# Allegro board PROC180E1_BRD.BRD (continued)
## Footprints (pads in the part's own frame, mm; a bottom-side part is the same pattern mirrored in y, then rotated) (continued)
CON_RCAJACK3_RCJ-02X_S_S_T_16
  rect 2.692x2.692 hole 1.981: 1(0,0)
  round 2.362 hole 1.676: 2(5.15,1.6)
  round 2.692 hole 1.981: 3(10.3,0)
CON_SD9_MEM2052-00-195-00_S_R_S_2
  rect 0.787x1.499 smd: 1(1.94,-3.66) 2(0.84,-3.26) 3(-0.26,-3.66) 4(-1.36,-3.86) 5(-2.46,-3.66) 6(-3.56,-3.86) 7(-4.66,-3.66) 8(-5.76,-3.66)
  rect 0.991x0.94 smd: 9(-3.56,7.425)
  rect 1.397x1.905 smd: SH1(6.6,-6.95) SH2(-6.55,-5.95)
  rect 1.295x1.397 smd: SH3(0.75,7.2)
  rect 1.194x1.397 smd: SH4(-5.008,7.2)
CON_USBA4_629104151_S_R_S_7-4
  round 1.092 hole 1.219 unplated: (-2.5,2.965) (2.5,2.965)
  rect 1.194x3.2 smd: 1(-3.5,6.665) 2(-1,6.665) 3(1,6.665) 4(3.5,6.665)
  oval 1.397x3.708 hole 0.711x2.997: SH1(-6.4,3.465) SH2(6.4,3.465)
CON_USBC24_2012670_S_R_S_3-9
  rect 0.305x0.762 smd: A1(-3,4.056) A2(-2.5,4.056) A3(-2,4.056) A4(-1.5,4.056) A5(-1,4.056) A6(-0.5,4.056) A7(0.5,4.056) A8(1,4.056) A9(1.5,4.056) A10(2,4.056) A11(2.5,4.056) A12(3,4.056) B2(2.25,2.356) B3(1.75,2.356) B4(1.25,2.356) B5(0.75,2.356) B6(0.25,2.356) B7(-0.25,2.356) B8(-0.75,2.356) B9(-1.25,2.356) B10(-1.75,2.356) B11(-2.25,2.356)
  rect 0.94x0.762 smd: B1(3.05,2.356) B12(-3.05,2.356)
  oval 1.194x2.21 hole 0.61x1.575: SH1(-4.32,3.246) SH2(4.32,3.246)
  oval 1.194x3.708 hole 0.61x2.083: SH3(4.62,-2.114) SH4(-4.62,-2.114)
DFN10_19-68_120X120_1
  rect 0.787x0.305 smd: 1(-1.5,1) 2(-1.5,0.5) 3(-1.5,0) 4(-1.5,-0.5) 5(-1.5,-1) 6(1.5,-1) 7(1.5,-0.5) 8(1.5,0) 9(1.5,0.5) 10(1.5,1)
  rect 1.753x2.515 smd: 11(0,0)
DIO_DFN0201_0-4
  rect 0.229x0.381 smd: 1(-0.22,0) 2(0.22,0)
DIO_DFN0402_0-5
  rect 0.356x0.61 smd: 1(-0.34,0) 2(0.34,0)
DIO_SOD323_1
  rect 0.914x0.508 smd: 1(-1.25,0) 2(1.25,0)
DIO_SOT23_123
  rect 1.016x0.61 smd: 1(-1.15,0.95) 2(-1.15,-0.95) 3(1.15,0)
DIO_SOT323-3_1-1
  rect 0.838x0.457 smd: 1(-1.05,0.65) 2(-1.05,-0.65) 3(1.05,0)
DSBGA12_15-74_60X70_0-4
  round 0.279 smd: A1(-0.4,0.6) A2(0,0.6) A3(0.4,0.6) B1(-0.4,0.2) B2(0,0.2) B3(0.4,0.2) C1(-0.4,-0.2) C2(0,-0.2) C3(0.4,-0.2) D1(-0.4,-0.6) D2(0,-0.6) D3(0.4,-0.6)
EMIFIL_BLM15A_0402_0-6
  rect 0.61x0.61 smd: 1(-0.46,0) 2(0.46,0)
EMIFIL_BLM18K_0603
  rect 0.94x1.194 smd: 1(-0.825,0) 2(0.825,0)
EMIFIL_BLM18P_0603_0-8
  rect 0.991x0.991 smd: 1(-0.75,0) 2(0.75,0)
EMIFIL_NFM15CC_0402_0-5
  rect 0.305x0.305 smd: 1(-0.5,0) 3(0.5,0)
  rect 0.254x0.762 smd: 2(0,0)
EMIFIL_NFM18C_0603_1-4
  rect 0.61x0.61 smd: 1(-0.8,0) 3(0.8,0)
  rect 0.406x1.219 smd: 2(0,0)
FBGA484_31-49_710X710_2-7
  round 0.457 smd: A1(-8.4,8.4) A2(-7.6,8.4) A3(-6.8,8.4) A4(-6,8.4) A5(-5.2,8.4) A6(-4.4,8.4) A7(-3.6,8.4) A8(-2.8,8.4) A9(-2,8.4) A10(-1.2,8.4) A11(-0.4,8.4) A12(0.4,8.4) A13(1.2,8.4) A14(2,8.4) A15(2.8,8.4) A16(3.6,8.4) A17(4.4,8.4) A18(5.2,8.4) A19(6,8.4) A20(6.8,8.4) A21(7.6,8.4) A22(8.4,8.4) AA1(-8.4,-7.6) AA2(-7.6,-7.6) AA3(-6.8,-7.6) AA4(-6,-7.6) AA5(-5.2,-7.6) AA6(-4.4,-7.6) AA7(-3.6,-7.6) AA8(-2.8,-7.6) AA9(-2,-7.6) AA10(-1.2,-7.6) AA11(-0.4,-7.6) AA12(0.4,-7.6) AA13(1.2,-7.6) AA14(2,-7.6) AA15(2.8,-7.6) AA16(3.6,-7.6) AA17(4.4,-7.6) AA18(5.2,-7.6) AA19(6,-7.6) AA20(6.8,-7.6) AA21(7.6,-7.6) AA22(8.4,-7.6) AB1(-8.4,-8.4) AB2(-7.6,-8.4) AB3(-6.8,-8.4) AB4(-6,-8.4) AB5(-5.2,-8.4) AB6(-4.4,-8.4) AB7(-3.6,-8.4) AB8(-2.8,-8.4) AB9(-2,-8.4) AB10(-1.2,-8.4) AB11(-0.4,-8.4) AB12(0.4,-8.4) AB13(1.2,-8.4) AB14(2,-8.4) AB15(2.8,-8.4) AB16(3.6,-8.4) AB17(4.4,-8.4) AB18(5.2,-8.4) AB19(6,-8.4) AB20(6.8,-8.4) AB21(7.6,-8.4) AB22(8.4,-8.4) B1(-8.4,7.6) B2(-7.6,7.6) B3(-6.8,7.6) B4(-6,7.6) B5(-5.2,7.6) B6(-4.4,7.6) B7(-3.6,7.6) B8(-2.8,7.6) B9(-2,7.6) B10(-1.2,7.6) B11(-0.4,7.6) B12(0.4,7.6) B13(1.2,7.6) B14(2,7.6) B15(2.8,7.6) B16(3.6,7.6) B17(4.4,7.6) B18(5.2,7.6) B19(6,7.6) B20(6.8,7.6) B21(7.6,7.6) B22(8.4,7.6) C1(-8.4,6.8) C2(-7.6,6.8) C3(-6.8,6.8) C4(-6,6.8) C5(-5.2,6.8) C6(-4.4,6.8) C7(-3.6,6.8) C8(-2.8,6.8) C9(-2,6.8) C10(-1.2,6.8) C11(-0.4,6.8) C12(0.4,6.8) C13(1.2,6.8) C14(2,6.8) C15(2.8,6.8) C16(3.6,6.8) C17(4.4,6.8) C18(5.2,6.8) C19(6,6.8) C20(6.8,6.8) C21(7.6,6.8) C22(8.4,6.8) D1(-8.4,6) D2(-7.6,6) D3(-6.8,6) D4(-6,6) D5(-5.2,6) D6(-4.4,6) D7(-3.6,6) D8(-2.8,6) D9(-2,6) D10(-1.2,6) D11(-0.4,6) D12(0.4,6) D13(1.2,6) D14(2,6) D15(2.8,6) D16(3.6,6) D17(4.4,6) D18(5.2,6) D19(6,6) D20(6.8,6) D21(7.6,6) D22(8.4,6) E1(-8.4,5.2) E2(-7.6,5.2) E3(-6.8,5.2) E4(-6,5.2) E5(-5.2,5.2) E6(-4.4,5.2) E7(-3.6,5.2) E8(-2.8,5.2) E9(-2,5.2) E10(-1.2,5.2) E11(-0.4,5.2) E12(0.4,5.2) E13(1.2,5.2) E14(2,5.2) E15(2.8,5.2) E16(3.6,5.2) E17(4.4,5.2) E18(5.2,5.2) E19(6,5.2) E20(6.8,5.2) E21(7.6,5.2) E22(8.4,5.2) F1(-8.4,4.4) F2(-7.6,4.4) F3(-6.8,4.4) F4(-6,4.4) F5(-5.2,4.4) F6(-4.4,4.4) F7(-3.6,4.4) F8(-2.8,4.4) F9(-2,4.4) F10(-1.2,4.4) F11(-0.4,4.4) F12(0.4,4.4) F13(1.2,4.4) F14(2,4.4) F15(2.8,4.4) F16(3.6,4.4) F17(4.4,4.4) F18(5.2,4.4) F19(6,4.4) F20(6.8,4.4) F21(7.6,4.4) F22(8.4,4.4) G1(-8.4,3.6) G2(-7.6,3.6) G3(-6.8,3.6) G4(-6,3.6) G5(-5.2,3.6) G6(-4.4,3.6) G7(-3.6,3.6) G8(-2.8,3.6) G9(-2,3.6) G10(-1.2,3.6) G11(-0.4,3.6) G12(0.4,3.6) G13(1.2,3.6) G14(2,3.6) G15(2.8,3.6) G16(3.6,3.6) G17(4.4,3.6) G18(5.2,3.6) G19(6,3.6) G20(6.8,3.6) G21(7.6,3.6) G22(8.4,3.6) H1(-8.4,2.8) H2(-7.6,2.8) H3(-6.8,2.8) H4(-6,2.8) H5(-5.2,2.8) H6(-4.4,2.8) H7(-3.6,2.8) H8(-2.8,2.8) H9(-2,2.8) H10(-1.2,2.8) H11(-0.4,2.8) H12(0.4,2.8) H13(1.2,2.8) H14(2,2.8) H15(2.8,2.8) H16(3.6,2.8) H17(4.4,2.8) H18(5.2,2.8) H19(6,2.8) H20(6.8,2.8) H21(7.6,2.8) H22(8.4,2.8) J1(-8.4,2) J2(-7.6,2) J3(-6.8,2) J4(-6,2) J5(-5.2,2) J6(-4.4,2) J7(-3.6,2) J8(-2.8,2) J9(-2,2) J10(-1.2,2) J11(-0.4,2) J12(0.4,2) J13(1.2,2) J14(2,2) J15(2.8,2) J16(3.6,2) J17(4.4,2) J18(5.2,2) J19(6,2) J20(6.8,2) J21(7.6,2) J22(8.4,2) K1(-8.4,1.2) K2(-7.6,1.2) K3(-6.8,1.2) K4(-6,1.2) K5(-5.2,1.2) K6(-4.4,1.2) K7(-3.6,1.2) K8(-2.8,1.2) K9(-2,1.2) K10(-1.2,1.2) K11(-0.4,1.2) K12(0.4,1.2) K13(1.2,1.2) K14(2,1.2) K15(2.8,1.2) K16(3.6,1.2) K17(4.4,1.2) K18(5.2,1.2) K19(6,1.2) K20(6.8,1.2) K21(7.6,1.2) K22(8.4,1.2) L1(-8.4,0.4) L2(-7.6,0.4) L3(-6.8,0.4) L4(-6,0.4) L5(-5.2,0.4) L6(-4.4,0.4) L7(-3.6,0.4) L8(-2.8,0.4) L9(-2,0.4) L10(-1.2,0.4) L11(-0.4,0.4) L12(0.4,0.4) L13(1.2,0.4) L14(2,0.4) L15(2.8,0.4) L16(3.6,0.4) L17(4.4,0.4) L18(5.2,0.4) L19(6,0.4) L20(6.8,0.4) L21(7.6,0.4) L22(8.4,0.4) M1(-8.4,-0.4) M2(-7.6,-0.4) M3(-6.8,-0.4) M4(-6,-0.4) M5(-5.2,-0.4) M6(-4.4,-0.4) M7(-3.6,-0.4) M8(-2.8,-0.4) M9(-2,-0.4) M10(-1.2,-0.4) M11(-0.4,-0.4) M12(0.4,-0.4) M13(1.2,-0.4) M14(2,-0.4) M15(2.8,-0.4) M16(3.6,-0.4) M17(4.4,-0.4) M18(5.2,-0.4) M19(6,-0.4) M20(6.8,-0.4) M21(7.6,-0.4) M22(8.4,-0.4) N1(-8.4,-1.2) N2(-7.6,-1.2) N3(-6.8,-1.2) N4(-6,-1.2) N5(-5.2,-1.2) N6(-4.4,-1.2) N7(-3.6,-1.2) N8(-2.8,-1.2) N9(-2,-1.2) N10(-1.2,-1.2) N11(-0.4,-1.2) N12(0.4,-1.2) N13(1.2,-1.2) N14(2,-1.2) N15(2.8,-1.2) N16(3.6,-1.2) N17(4.4,-1.2) N18(5.2,-1.2) N19(6,-1.2) N20(6.8,-1.2) N21(7.6,-1.2) N22(8.4,-1.2) P1(-8.4,-2) P2(-7.6,-2) P3(-6.8,-2) P4(-6,-2) P5(-5.2,-2) P6(-4.4,-2) P7(-3.6,-2) P8(-2.8,-2) P9(-2,-2) P10(-1.2,-2) P11(-0.4,-2) P12(0.4,-2) P13(1.2,-2) P14(2,-2) P15(2.8,-2) P16(3.6,-2) P17(4.4,-2) P18(5.2,-2) P19(6,-2) P20(6.8,-2) P21(7.6,-2) P22(8.4,-2) R1(-8.4,-2.8) R2(-7.6,-2.8) R3(-6.8,-2.8) R4(-6,-2.8) R5(-5.2,-2.8) R6(-4.4,-2.8) R7(-3.6,-2.8) R8(-2.8,-2.8) R9(-2,-2.8) R10(-1.2,-2.8) R11(-0.4,-2.8) R12(0.4,-2.8) R13(1.2,-2.8) R14(2,-2.8) R15(2.8,-2.8) R16(3.6,-2.8) R17(4.4,-2.8) R18(5.2,-2.8) R19(6,-2.8) R20(6.8,-2.8) R21(7.6,-2.8) R22(8.4,-2.8) T1(-8.4,-3.6) T2(-7.6,-3.6) T3(-6.8,-3.6) T4(-6,-3.6) T5(-5.2,-3.6) T6(-4.4,-3.6) T7(-3.6,-3.6) T8(-2.8,-3.6) T9(-2,-3.6) T10(-1.2,-3.6) T11(-0.4,-3.6) T12(0.4,-3.6) T13(1.2,-3.6) T14(2,-3.6) T15(2.8,-3.6) T16(3.6,-3.6) T17(4.4,-3.6) T18(5.2,-3.6) T19(6,-3.6) T20(6.8,-3.6) T21(7.6,-3.6) T22(8.4,-3.6) U1(-8.4,-4.4) U2(-7.6,-4.4) U3(-6.8,-4.4) U4(-6,-4.4) U5(-5.2,-4.4) U6(-4.4,-4.4) U7(-3.6,-4.4) U8(-2.8,-4.4) U9(-2,-4.4) U10(-1.2,-4.4) U11(-0.4,-4.4) U12(0.4,-4.4) U13(1.2,-4.4) U14(2,-4.4) U15(2.8,-4.4) U16(3.6,-4.4) U17(4.4,-4.4) U18(5.2,-4.4) U19(6,-4.4) U20(6.8,-4.4) U21(7.6,-4.4) U22(8.4,-4.4) V1(-8.4,-5.2) V2(-7.6,-5.2) V3(-6.8,-5.2) V4(-6,-5.2) V5(-5.2,-5.2) V6(-4.4,-5.2) V7(-3.6,-5.2) V8(-2.8,-5.2) V9(-2,-5.2) V10(-1.2,-5.2) V11(-0.4,-5.2) V12(0.4,-5.2) V13(1.2,-5.2) V14(2,-5.2) V15(2.8,-5.2) V16(3.6,-5.2) V17(4.4,-5.2) V18(5.2,-5.2) V19(6,-5.2) V20(6.8,-5.2) V21(7.6,-5.2) V22(8.4,-5.2) W1(-8.4,-6) W2(-7.6,-6) W3(-6.8,-6) W4(-6,-6) W5(-5.2,-6) W6(-4.4,-6) W7(-3.6,-6) W8(-2.8,-6) W9(-2,-6) W10(-1.2,-6) W11(-0.4,-6) W12(0.4,-6) W13(1.2,-6) W14(2,-6) W15(2.8,-6) W16(3.6,-6) W17(4.4,-6) W18(5.2,-6) W19(6,-6) W20(6.8,-6) W21(7.6,-6) W22(8.4,-6) Y1(-8.4,-6.8) Y2(-7.6,-6.8) Y3(-6.8,-6.8) Y4(-6,-6.8) Y5(-5.2,-6.8) Y6(-4.4,-6.8) Y7(-3.6,-6.8) Y8(-2.8,-6.8) Y9(-2,-6.8) Y10(-1.2,-6.8) Y11(-0.4,-6.8) Y12(0.4,-6.8) Y13(1.2,-6.8) Y14(2,-6.8) Y15(2.8,-6.8) Y16(3.6,-6.8) Y17(4.4,-6.8) Y18(5.2,-6.8) Y19(6,-6.8) Y20(6.8,-6.8) Y21(7.6,-6.8) Y22(8.4,-6.8)
HDR_1X2_90120-0122_S_T_5-6
  rect 1.702x1.702 hole 1.016: 1(0,0)
  round 1.702 hole 1.016: 2(-2.54,0)
HDR_1X2_61300211121_S_T_8-6
  rect 1.803x1.803 hole 1.118: 1(0,0)
  round 1.803 hole 1.118: 2(-2.54,0)
HDR_1X3_100_S_T
  rect 1.803x1.803 hole 1.118: 1(0,0)
  round 1.803 hole 1.118: 2(-2.54,0) 3(-5.08,0)
HDR_1X6_61300611121_S_T_8-6
  rect 1.803x1.803 hole 1.118: 1(0,0)
  round 1.803 hole 1.118: 2(-2.54,0) 3(-5.08,0) 4(-7.62,0) 5(-10.16,0) 6(-12.7,0)
HDR_2X5_PEC05DAAN_S_T_8-6
  rect 1.702x1.702 hole 1.016: 1(0,0)
  round 1.702 hole 1.016: 2(0,2.54) 3(2.54,0) 4(2.54,2.54) 5(5.08,0) 6(5.08,2.54) 7(7.62,0) 8(7.62,2.54) 9(10.16,0) 10(10.16,2.54)
HDR_2X10_FTR-110-51-D-06_S_S_8-7
  rect 0.711x3.124 smd: 1(-5.715,-2.578) 2(-5.715,2.578) 3(-4.445,-2.578) 4(-4.445,2.578) 5(-3.175,-2.578) 7(-1.905,-2.578) 8(-1.905,2.578) 9(-0.635,-2.578) 10(-0.635,2.578) 11(0.635,-2.578) 12(0.635,2.578) 13(1.905,-2.578) 14(1.905,2.578) 15(3.175,-2.578) 16(3.175,2.578) 17(4.445,-2.578) 18(4.445,2.578) 19(5.715,-2.578) 20(5.715,2.578)
IND4_DLW21H_90X60_SMD_1-4
  rect 0.889x0.356 smd: 1(-0.85,-0.425) 2(0.85,-0.425) 3(0.85,0.425) 4(-0.85,0.425)
IND0806
  rect 1.219x1.803 smd: 1(-0.85,0) 2(0.85,0)
IND0806_1-2
  rect 1.219x1.803 smd: 1(-0.85,0) 2(0.85,0)
IND1210_1-2
  rect 1.346x2.794 smd: 1(-1.6,0) 2(1.6,0)
IND_XAL7070_300X310_SMD_7
  rect 1.93x6.502 smd: 1(-2.41,0) 2(2.41,0)
IND_XFL4020_170X170_SMD_2-1
  rect 0.991x3.404 smd: 1(-1.185,0) 2(1.185,0)
INDP1210
  rect 1.803x2.007 smd: 1(-1.4,0) 2(1.4,0)
LED_150040GS73220_40X20_SMD_0-4
  rect 0.406x0.457 smd: 1(-0.5,0) 2(0.5,0)
LED_150080VS75000_80X50_SMD_0-8
  rect 1.092x1.194 smd: 1(-1.05,0) 2(1.05,0)
LQFP64_19-68_390X390_1-6
  rect 1.499x0.305 smd: 1(-5.7,3.75) 2(-5.7,3.25) 3(-5.7,2.75) 4(-5.7,2.25) 5(-5.7,1.75) 6(-5.7,1.25) 7(-5.7,0.75) 8(-5.7,0.25) 9(-5.7,-0.25) 10(-5.7,-0.75) 11(-5.7,-1.25) 12(-5.7,-1.75) 13(-5.7,-2.25) 14(-5.7,-2.75) 15(-5.7,-3.25) 16(-5.7,-3.75) 33(5.7,-3.75) 34(5.7,-3.25) 35(5.7,-2.75) 36(5.7,-2.25) 37(5.7,-1.75) 38(5.7,-1.25) 39(5.7,-0.75) 40(5.7,-0.25) 41(5.7,0.25) 42(5.7,0.75) 43(5.7,1.25) 44(5.7,1.75) 45(5.7,2.25) 46(5.7,2.75) 47(5.7,3.25) 48(5.7,3.75)
  rect 0.305x1.499 smd: 17(-3.75,-5.7) 18(-3.25,-5.7) 19(-2.75,-5.7) 20(-2.25,-5.7) 21(-1.75,-5.7) 22(-1.25,-5.7) 23(-0.75,-5.7) 24(-0.25,-5.7) 25(0.25,-5.7) 26(0.75,-5.7) 27(1.25,-5.7) 28(1.75,-5.7) 29(2.25,-5.7) 30(2.75,-5.7) 31(3.25,-5.7) 32(3.75,-5.7) 49(3.75,5.7) 50(3.25,5.7) 51(2.75,5.7) 52(2.25,5.7) 53(1.75,5.7) 54(1.25,5.7) 55(0.75,5.7) 56(0.25,5.7) 57(-0.25,5.7) 58(-0.75,5.7) 59(-1.25,5.7) 60(-1.75,5.7) 61(-2.25,5.7) 62(-2.75,5.7) 63(-3.25,5.7) 64(-3.75,5.7)
MOD5_PLR135T10_10-3
  rect 1.575x1.575 hole 0.864: 1(0,0)
  round 1.575 hole 0.864: 2(-2.54,0) 3(-5.08,0)
  round 1.88 hole 1.168: 4(0,2.63) 5(-5.08,2.63)
MSOP8_25-59_125X125_1-1
  rect 1.448x0.457 smd: 1(-2.2,0.975) 2(-2.2,0.325) 3(-2.2,-0.325) 4(-2.2,-0.975) 5(2.2,-0.975) 6(2.2,-0.325) 7(2.2,0.325) 8(2.2,0.975)
MSOP10_19-68_120X120_1-1
  rect 1.448x0.305 smd: 1(-2.2,1) 2(-2.2,0.5) 3(-2.2,0) 4(-2.2,-0.5) 5(-2.2,-1) 6(2.2,-1) 7(2.2,-0.5) 8(2.2,0) 9(2.2,0.5) 10(2.2,1)
QFN20_19-68_160X160_0-9_EP2-7
  rect 0.787x0.305 smd: 1(-2,1) 2(-2,0.5) 3(-2,0) 4(-2,-0.5) 5(-2,-1) 11(2,-1) 12(2,-0.5) 13(2,0) 14(2,0.5) 15(2,1)
  rect 0.305x0.787 smd: 6(-1,-2) 7(-0.5,-2) 8(0,-2) 9(0.5,-2) 10(1,-2) 16(1,2) 17(0.5,2) 18(0,2) 19(-0.5,2) 20(-1,2)
  rect 2.692x2.692 smd: 21(0,0)
QFN24_19-68_220X140_1
  rect 0.838x0.279 smd: 1(-2.725,-0.75) 12(2.725,-0.75) 13(2.725,0.75) 24(-2.725,0.75)
  rect 0.279x0.838 smd: 2(-2.25,-1.725) 3(-1.75,-1.725) 4(-1.25,-1.725) 5(-0.75,-1.725) 6(-0.25,-1.725) 7(0.25,-1.725) 8(0.75,-1.725) 9(1.25,-1.725) 10(1.75,-1.725) 11(2.25,-1.725) 14(2.25,1.725) 15(1.75,1.725) 16(1.25,1.725) 17(0.75,1.725) 18(0.25,1.725) 19(-0.25,1.725) 20(-0.75,1.725) 21(-1.25,1.725) 22(-1.75,1.725) 23(-2.25,1.725)
  custom 0.508x0.508 smd: 25(0,0)
QFN24_TAD5212IRGER_160X160_1
  rect 0.787x0.305 smd: 1(-2,1.25) 2(-2,0.75) 3(-2,0.25) 4(-2,-0.25) 5(-2,-0.75) 6(-2,-1.25) 13(2,-1.25) 14(2,-0.75) 15(2,-0.25) 16(2,0.25) 17(2,0.75) 18(2,1.25)
  rect 0.305x0.787 smd: 7(-1.25,-2) 8(-0.75,-2) 9(-0.25,-2) 10(0.25,-2) 11(0.75,-2) 12(1.25,-2) 19(1.25,2) 20(0.75,2) 21(0.25,2) 22(-0.25,2) 23(-0.75,2) 24(-1.25,2)
  rect 2.21x2.21 smd: 25(0,0)
  rect 0.254x0.254 smd: A1(-1.725,1.725) A2(-1.725,-1.725) A3(1.725,-1.725) A4(1.725,1.725)
QFN32_19-68_200X200
  rect 0.838x0.305 smd: 1(-2.5,1.75) 2(-2.5,1.25) 3(-2.5,0.75) 4(-2.5,0.25) 5(-2.5,-0.25) 6(-2.5,-0.75) 7(-2.5,-1.25) 8(-2.5,-1.75) 17(2.5,-1.75) 18(2.5,-1.25) 19(2.5,-0.75) 20(2.5,-0.25) 21(2.5,0.25) 22(2.5,0.75) 23(2.5,1.25) 24(2.5,1.75)
  rect 0.305x0.838 smd: 9(-1.75,-2.5) 10(-1.25,-2.5) 11(-0.75,-2.5) 12(-0.25,-2.5) 13(0.25,-2.5) 14(0.75,-2.5) 15(1.25,-2.5) 16(1.75,-2.5) 25(1.75,2.5) 26(1.25,2.5) 27(0.75,2.5) 28(0.25,2.5) 29(-0.25,2.5) 30(-0.75,2.5) 31(-1.25,2.5) 32(-1.75,2.5)
  rect 3.556x3.556 smd: 33(0,0)
QFN32_19-68_200X200_0-8_EP3-6
  rect 0.787x0.305 smd: 1(-2.5,1.75) 2(-2.5,1.25) 3(-2.5,0.75) 4(-2.5,0.25) 5(-2.5,-0.25) 6(-2.5,-0.75) 7(-2.5,-1.25) 8(-2.5,-1.75) 17(2.5,-1.75) 18(2.5,-1.25) 19(2.5,-0.75) 20(2.5,-0.25) 21(2.5,0.25) 22(2.5,0.75) 23(2.5,1.25) 24(2.5,1.75)
  rect 0.305x0.787 smd: 9(-1.75,-2.5) 10(-1.25,-2.5) 11(-0.75,-2.5) 12(-0.25,-2.5) 13(0.25,-2.5) 14(0.75,-2.5) 15(1.25,-2.5) 16(1.75,-2.5) 25(1.75,2.5) 26(1.25,2.5) 27(0.75,2.5) 28(0.25,2.5) 29(-0.25,2.5) 30(-0.75,2.5) 31(-1.25,2.5) 32(-1.75,2.5)
  rect 3.607x3.607 smd: 33(0,0)
QFN48_19-68_280X280_1_EP5-4
  rect 0.813x0.305 smd: 1(-3.5,2.75) 2(-3.5,2.25) 3(-3.5,1.75) 4(-3.5,1.25) 5(-3.5,0.75) 6(-3.5,0.25) 7(-3.5,-0.25) 8(-3.5,-0.75) 9(-3.5,-1.25) 10(-3.5,-1.75) 11(-3.5,-2.25) 12(-3.5,-2.75) 25(3.5,-2.75) 26(3.5,-2.25) 27(3.5,-1.75) 28(3.5,-1.25) 29(3.5,-0.75) 30(3.5,-0.25) 31(3.5,0.25) 32(3.5,0.75) 33(3.5,1.25) 34(3.5,1.75) 35(3.5,2.25) 36(3.5,2.75)
  rect 0.305x0.813 smd: 13(-2.75,-3.5) 14(-2.25,-3.5) 15(-1.75,-3.5) 16(-1.25,-3.5) 17(-0.75,-3.5) 18(-0.25,-3.5) 19(0.25,-3.5) 20(0.75,-3.5) 21(1.25,-3.5) 22(1.75,-3.5) 23(2.25,-3.5) 24(2.75,-3.5) 37(2.75,3.5) 38(2.25,3.5) 39(1.75,3.5) 40(1.25,3.5) 41(0.75,3.5) 42(0.25,3.5) 43(-0.25,3.5) 44(-0.75,3.5) 45(-1.25,3.5) 46(-1.75,3.5) 47(-2.25,3.5) 48(-2.75,3.5)
  rect 5.41x5.41 smd: 49(0,0)
RES0201_0-5
  rect 0.356x0.33 smd: 1(-0.28,0) 2(0.28,0)
RES0402_0-5
  rect 0.559x0.635 smd: 1(-0.49,0) 2(0.49,0)
RES0603_0-75
  rect 0.635x0.991 smd: 1(-0.74,0) 2(0.74,0)
RES0805_0-75
  rect 1.194x1.448 smd: 1(-0.95,0) 2(0.95,0)
RES1206_1
  rect 1.067x1.753 smd: 1(-1.45,0) 2(1.45,0)
RES_CST0612_0612-4_0-9
  rect 0.991x2.311 smd: 1(-0.85,0.6) 4(0.85,0.6)
  rect 0.991x0.787 smd: 2(-0.85,-1.35) 3(0.85,-1.35)
RES_KRL3216T4_1206-4_0-7
  rect 1.143x0.356 smd: 1(-0.775,1.5) 4(0.775,1.5)
  rect 1.143x2.692 smd: 2(-0.775,-0.325) 3(0.775,-0.325)
RESA_EXB_0201-2_0-5
  rect 0.203x0.305 smd: 1(-0.25,-0.275) 2(0.25,-0.275) 3(0.25,0.275) 4(-0.25,0.275)
RESA_EXB_0201-4_0-5
  rect 0.203x0.305 smd: 1(-0.6,-0.275) 2(-0.2,-0.275) 3(0.2,-0.275) 4(0.6,-0.275) 5(0.6,0.275) 6(0.2,0.275) 7(-0.2,0.275) 8(-0.6,0.275)
SC70-5
  rect 0.94x0.406 smd: 1(-1.1,0.65) 2(-1.1,0) 3(-1.1,-0.65) 4(1.1,-0.65) 5(1.1,0.65)
SC70-5_1-1
  rect 0.94x0.406 smd: 1(-1.1,0.65) 2(-1.1,0) 3(-1.1,-0.65) 4(1.1,-0.65) 5(1.1,0.65)
SOIC8_1-8
  rect 1.549x0.61 smd: 1(-2.7,1.905) 2(-2.7,0.635) 3(-2.7,-0.635) 4(-2.7,-1.905) 5(2.7,-1.905) 6(2.7,-0.635) 7(2.7,0.635) 8(2.7,1.905)
SON6_19-68_40X60_PB_0-6
  rect 0.356x0.305 smd: 1(-0.3,0.5) 2(-0.3,0) 3(-0.3,-0.5) 4(0.3,-0.5) 5(0.3,0) 6(0.3,0.5)
SON6_25-59_85X85
  rect 0.61x0.356 smd: 1(-1.05,0.65) 2(-1.05,0) 3(-1.05,-0.65) 4(1.05,-0.65) 5(1.05,0) 6(1.05,0.65)
  rect 1.092x1.702 smd: 7(0,0)
SON6_25-59_85X85_0-8
  rect 0.61x0.356 smd: 1(-1.05,0.65) 2(-1.05,0) 3(-1.05,-0.65) 4(1.05,-0.65) 5(1.05,0) 6(1.05,0.65)
  rect 1.067x1.702 smd: 7(0,0)
SON6_CSD17313Q2_80X80
  rect 0.406x0.457 smd: 1(-0.65,-0.923) 2(0,-0.923) 3(0.65,-0.923) 4(0.65,0.923) 5(0,0.923) 6(-0.65,0.923)
  rect 0.406x0.864 smd: 7(0.65,0.096)
  rect 1.041x1.092 smd: 8(-0.325,0)
SON6_SN74LVC2G17_40X60_0-6
  rect 0.356x0.203 smd: 1(-0.275,0.5)
  rect 0.305x0.203 smd: 2(-0.3,0) 3(-0.3,-0.5) 4(0.3,-0.5) 5(0.3,0) 6(0.3,0.5)
SON8_25-59_130X130_1
  rect 0.762x0.356 smd: 1(-1.45,0.975) 2(-1.45,0.325) 3(-1.45,-0.325) 4(-1.45,-0.975) 5(1.45,-0.975) 6(1.45,-0.325) 7(1.45,0.325) 8(1.45,0.975)
  rect 1.753x2.515 smd: 9(0,0)
SOT23-5
  rect 0.889x0.559 smd: 1(-1.2,0.95) 2(-1.2,0) 3(-1.2,-0.95) 4(1.2,-0.95) 5(1.2,0.95)
SOT23-5_1-5
  rect 1.092x0.61 smd: 1(-1.3,0.95) 2(-1.3,0) 3(-1.3,-0.95) 4(1.3,-0.95) 5(1.3,0.95)
SOT23-6
  rect 1.041x0.61 smd: 1(-1.35,0.95) 2(-1.35,0) 3(-1.35,-0.95) 4(1.35,-0.95) 5(1.35,0) 6(1.35,0.95)
SOT23-6_1-5
  rect 1.092x0.61 smd: 1(-1.35,0.95) 2(-1.35,0) 3(-1.35,-0.95) 4(1.35,-0.95) 5(1.35,0) 6(1.35,0.95)
SOT23-123_1-2
  rect 1.016x0.61 smd: 1(-1.15,0.95) 2(-1.15,-0.95) 3(1.15,0)
SOT553-5_0-6
  rect 0.66x0.254 smd: 1(-0.74,0.5) 2(-0.74,0) 3(-0.74,-0.5) 4(0.74,-0.5) 5(0.74,0.5)
SW4_49-99_150X230_SMD_2-7
  rect 0.762x1.27 smd: 1(-0.635,-3.81) 2(0.635,-3.81) 3(0.635,3.81) 4(-0.635,3.81)
SW4_100X216_200X200_SMD_4-2
  rect 1.27x1.27 smd: 1(-1.27,-2.75) 2(1.27,-2.75) 3(1.27,2.75) 4(-1.27,2.75)
SW16_416131160808_460X230_SMD_2-7
  rect 0.762x1.27 smd: 1(-4.445,-3.81) 2(-3.175,-3.81) 3(-1.905,-3.81) 4(-0.635,-3.81) 5(0.635,-3.81) 6(1.905,-3.81) 7(3.175,-3.81) 8(4.445,-3.81) 9(4.445,3.81) 10(3.175,3.81) 11(1.905,3.81) 12(0.635,3.81) 13(-0.635,3.81) 14(-1.905,3.81) 15(-3.175,3.81) 16(-4.445,3.81)
TO_SOT23-123
  rect 1.016x1.397 smd: 1(-0.95,-1.1) 2(0.95,-1.1) 3(0,1.1)
TP20_SMD
  round 0.457 smd: 1(0,0)
TP30_SMD
  round 0.762 smd: 1(0,0)
TP40_SMD
  round 1.016 smd: 1(0,0)
TP_40X65
  round 1.651 hole 1.016: 1(0,0)
TP_CIR40D30
  round 1.016 hole 0.762: 1(0,0)
TQFP48_19-68_280X280_1-2
  rect 1.499x0.305 smd: 1(-4.2,2.75) 2(-4.2,2.25) 3(-4.2,1.75) 4(-4.2,1.25) 5(-4.2,0.75) 6(-4.2,0.25) 7(-4.2,-0.25) 8(-4.2,-0.75) 9(-4.2,-1.25) 10(-4.2,-1.75) 11(-4.2,-2.25) 12(-4.2,-2.75) 25(4.2,-2.75) 26(4.2,-2.25) 27(4.2,-1.75) 28(4.2,-1.25) 29(4.2,-0.75) 30(4.2,-0.25) 31(4.2,0.25) 32(4.2,0.75) 33(4.2,1.25) 34(4.2,1.75) 35(4.2,2.25) 36(4.2,2.75)
  rect 0.305x1.499 smd: 13(-2.75,-4.2) 14(-2.25,-4.2) 15(-1.75,-4.2) 16(-1.25,-4.2) 17(-0.75,-4.2) 18(-0.25,-4.2) 19(0.25,-4.2) 20(0.75,-4.2) 21(1.25,-4.2) 22(1.75,-4.2) 23(2.25,-4.2) 24(2.75,-4.2) 37(2.75,4.2) 38(2.25,4.2) 39(1.75,4.2) 40(1.25,4.2) 41(0.75,4.2) 42(0.25,4.2) 43(-0.25,4.2) 44(-0.75,4.2) 45(-1.25,4.2) 46(-1.75,4.2) 47(-2.25,4.2) 48(-2.75,4.2)
TQFP128_15-74_550X550_1-2
  rect 1.499x0.203 smd: 1(-7.7,6.2) 2(-7.7,5.8) 3(-7.7,5.4) 4(-7.7,5) 5(-7.7,4.6) 6(-7.7,4.2) 7(-7.7,3.8) 8(-7.7,3.4) 9(-7.7,3) 10(-7.7,2.6) 11(-7.7,2.2) 12(-7.7,1.8) 13(-7.7,1.4) 14(-7.7,1) 15(-7.7,0.6) 16(-7.7,0.2) 17(-7.7,-0.2) 18(-7.7,-0.6) 19(-7.7,-1) 20(-7.7,-1.4) 21(-7.7,-1.8) 22(-7.7,-2.2) 23(-7.7,-2.6) 24(-7.7,-3) 25(-7.7,-3.4) 26(-7.7,-3.8) 27(-7.7,-4.2) 28(-7.7,-4.6) 29(-7.7,-5) 30(-7.7,-5.4) 31(-7.7,-5.8) 32(-7.7,-6.2) 65(7.7,-6.2) 66(7.7,-5.8) 67(7.7,-5.4) 68(7.7,-5) 69(7.7,-4.6) 70(7.7,-4.2) 71(7.7,-3.8) 72(7.7,-3.4) 73(7.7,-3) 74(7.7,-2.6) 75(7.7,-2.2) 76(7.7,-1.8) 77(7.7,-1.4) 78(7.7,-1) 79(7.7,-0.6) 80(7.7,-0.2) 81(7.7,0.2) 82(7.7,0.6) 83(7.7,1) 84(7.7,1.4) 85(7.7,1.8) 86(7.7,2.2) 87(7.7,2.6) 88(7.7,3) 89(7.7,3.4) 90(7.7,3.8) 91(7.7,4.2) 92(7.7,4.6) 93(7.7,5) 94(7.7,5.4) 95(7.7,5.8) 96(7.7,6.2)
  rect 0.203x1.499 smd: 33(-6.2,-7.7) 34(-5.8,-7.7) 35(-5.4,-7.7) 36(-5,-7.7) 37(-4.6,-7.7) 38(-4.2,-7.7) 39(-3.8,-7.7) 40(-3.4,-7.7) 41(-3,-7.7) 42(-2.6,-7.7) 43(-2.2,-7.7) 44(-1.8,-7.7) 45(-1.4,-7.7) 46(-1,-7.7) 47(-0.6,-7.7) 48(-0.2,-7.7) 49(0.2,-7.7) 50(0.6,-7.7) 51(1,-7.7) 52(1.4,-7.7) 53(1.8,-7.7) 54(2.2,-7.7) 55(2.6,-7.7) 56(3,-7.7) 57(3.4,-7.7) 58(3.8,-7.7) 59(4.2,-7.7) 60(4.6,-7.7) 61(5,-7.7) 62(5.4,-7.7) 63(5.8,-7.7) 64(6.2,-7.7) 97(6.2,7.7) 98(5.8,7.7) 99(5.4,7.7) 100(5,7.7) 101(4.6,7.7) 102(4.2,7.7) 103(3.8,7.7) 104(3.4,7.7) 105(3,7.7) 106(2.6,7.7) 107(2.2,7.7) 108(1.8,7.7) 109(1.4,7.7) 110(1,7.7) 111(0.6,7.7) 112(0.2,7.7) 113(-0.2,7.7) 114(-0.6,7.7) 115(-1,7.7) 116(-1.4,7.7) 117(-1.8,7.7) 118(-2.2,7.7) 119(-2.6,7.7) 120(-3,7.7) 121(-3.4,7.7) 122(-3.8,7.7) 123(-4.2,7.7) 124(-4.6,7.7) 125(-5,7.7) 126(-5.4,7.7) 127(-5.8,7.7) 128(-6.2,7.7)
TSSOP8_25-59_125X180_1-2
  rect 1.499x0.457 smd: 1(-2.9,0.975) 2(-2.9,0.325) 3(-2.9,-0.325) 4(-2.9,-0.975) 5(2.9,-0.975) 6(2.9,-0.325) 7(2.9,0.325) 8(2.9,0.975)
TSSOP14_25-59_205X180_1-2
  rect 1.499x0.457 smd: 1(-2.9,1.95) 2(-2.9,1.3) 3(-2.9,0.65) 4(-2.9,0) 5(-2.9,-0.65) 6(-2.9,-1.3) 7(-2.9,-1.95) 8(2.9,-1.95) 9(2.9,-1.3) 10(2.9,-0.65) 11(2.9,0) 12(2.9,0.65) 13(2.9,1.3) 14(2.9,1.95)
TVSOP14_15-74_180X150_1-2
  rect 1.499x0.203 smd: 1(-2.9,1.2) 2(-2.9,0.8) 3(-2.9,0.4) 4(-2.9,0) 5(-2.9,-0.4) 6(-2.9,-0.8) 7(-2.9,-1.2) 8(2.9,-1.2) 9(2.9,-0.8) 10(2.9,-0.4) 11(2.9,0) 12(2.9,0.4) 13(2.9,0.8) 14(2.9,1.2)
UDFN8_19-68_120X80_0-6
  rect 0.813x0.305 smd: 1(-1.45,0.75) 2(-1.45,0.25) 3(-1.45,-0.25) 4(-1.45,-0.75) 5(1.45,-0.75) 6(1.45,-0.25) 7(1.45,0.25) 8(1.45,0.75)
  rect 1.397x1.6 smd: 9(0,0)
unnamed
  round 0.686 hole 0.813 unplated: (-1.27,1.076) (0,1.076) (1.27,1.076)
unnamed#2
  round 2.616 hole 2.743 unplated: (0,0)
unnamed#4
  round 1.6 hole 1.727 unplated: (-10.362,10.362) (-10.362,-10.362) (10.362,10.362) (10.362,-10.362)
  round 0.737 hole 0.864 unplated: (-10.362,-5.282) (10.362,7.822)
UQFN10_19-68_80X60_0-6
  rect 0.584x0.305 smd: 1(-0.635,0.75) 4(-0.635,-0.75) 6(0.635,-0.75) 9(0.635,0.75)
  rect 0.584x0.254 smd: 2(-0.635,0.25) 3(-0.635,-0.25) 7(0.635,-0.25) 8(0.635,0.25)
  rect 0.305x0.635 smd: 5(0,-0.86) 10(0,0.86)
UQFN12_15-74_80X70
  rect 0.686x0.33 smd: 1(-0.655,0.85)
  rect 0.686x0.229 smd: 2(-0.655,0.4) 3(-0.655,0) 4(-0.655,-0.4) 5(-0.655,-0.8) 7(0.655,-0.8) 8(0.655,-0.4) 9(0.655,0) 10(0.655,0.4) 11(0.655,0.8)
  rect 0.229x0.686 smd: 6(0,-0.805) 12(0,0.805)
UQFN16_TMUX1574_70X100_0-6
  rect 0.711x0.203 smd: 1(-0.75,0.6)
  rect 0.61x0.203 smd: 2(-0.8,0.2) 3(-0.8,-0.2) 4(-0.8,-0.6) 9(0.8,-0.6) 10(0.8,-0.2) 11(0.8,0.2) 12(0.8,0.6)
  rect 0.203x0.61 smd: 5(-0.6,-1.2) 6(-0.2,-1.2) 7(0.2,-1.2) 8(0.6,-1.2) 13(0.6,1.2) 14(0.2,1.2) 15(-0.2,1.2) 16(-0.6,1.2)
VFBGA153_19-68_460X520_0-9
  round 0.203 smd: A1(-3.25,3.25) A2(-2.75,3.25) A3(-2.25,3.25) A4(-1.75,3.25) A5(-1.25,3.25) A6(-0.75,3.25) B1(-3.25,2.75) C1(-3.25,2.25) D1(-3.25,1.75) M1(-3.25,-2.25) N1(-3.25,-2.75) P1(-3.25,-3.25)
  round 0.254 smd: A7(-0.25,3.25) A8(0.25,3.25) A9(0.75,3.25) A10(1.25,3.25) A11(1.75,3.25) A12(2.25,3.25) A13(2.75,3.25) A14(3.25,3.25) B2(-2.75,2.75) B3(-2.25,2.75) B4(-1.75,2.75) B5(-1.25,2.75) B6(-0.75,2.75) B7(-0.25,2.75) B8(0.25,2.75) B9(0.75,2.75) B10(1.25,2.75) B11(1.75,2.75) B12(2.25,2.75) B13(2.75,2.75) B14(3.25,2.75) C2(-2.75,2.25) C3(-2.25,2.25) C4(-1.75,2.25) C5(-1.25,2.25) C6(-0.75,2.25) C7(-0.25,2.25) C8(0.25,2.25) C9(0.75,2.25) C10(1.25,2.25) C11(1.75,2.25) C12(2.25,2.25) C13(2.75,2.25) C14(3.25,2.25) D2(-2.75,1.75) D3(-2.25,1.75) D4(-1.75,1.75) D12(2.25,1.75) D13(2.75,1.75) D14(3.25,1.75) E1(-3.25,1.25) E2(-2.75,1.25) E3(-2.25,1.25) E5(-1.25,1.25) E6(-0.75,1.25) E7(-0.25,1.25) E8(0.25,1.25) E9(0.75,1.25) E10(1.25,1.25) E12(2.25,1.25) E13(2.75,1.25) E14(3.25,1.25) F1(-3.25,0.75) F2(-2.75,0.75) F3(-2.25,0.75) F5(-1.25,0.75) F10(1.25,0.75) F12(2.25,0.75) F13(2.75,0.75) F14(3.25,0.75) G1(-3.25,0.25) G2(-2.75,0.25) G3(-2.25,0.25) G5(-1.25,0.25) G10(1.25,0.25) G12(2.25,0.25) G13(2.75,0.25) G14(3.25,0.25) H1(-3.25,-0.25) H2(-2.75,-0.25) H3(-2.25,-0.25) H5(-1.25,-0.25) H10(1.25,-0.25) H12(2.25,-0.25) H13(2.75,-0.25) H14(3.25,-0.25) J1(-3.25,-0.75) J2(-2.75,-0.75) J3(-2.25,-0.75) J5(-1.25,-0.75) J10(1.25,-0.75) J12(2.25,-0.75) J13(2.75,-0.75) J14(3.25,-0.75) K1(-3.25,-1.25) K2(-2.75,-1.25) K3(-2.25,-1.25) K5(-1.25,-1.25) K6(-0.75,-1.25) K7(-0.25,-1.25) K8(0.25,-1.25) K9(0.75,-1.25) K10(1.25,-1.25) K12(2.25,-1.25) K13(2.75,-1.25) K14(3.25,-1.25) L1(-3.25,-1.75) L2(-2.75,-1.75) L3(-2.25,-1.75) L12(2.25,-1.75) L13(2.75,-1.75) L14(3.25,-1.75) M2(-2.75,-2.25) M3(-2.25,-2.25) M4(-1.75,-2.25) M5(-1.25,-2.25) M6(-0.75,-2.25) M7(-0.25,-2.25) M8(0.25,-2.25) M9(0.75,-2.25) M10(1.25,-2.25) M11(1.75,-2.25) M12(2.25,-2.25) M13(2.75,-2.25) M14(3.25,-2.25) N2(-2.75,-2.75) N3(-2.25,-2.75) N4(-1.75,-2.75) N5(-1.25,-2.75) N6(-0.75,-2.75) N7(-0.25,-2.75) N8(0.25,-2.75) N9(0.75,-2.75) N10(1.25,-2.75) N11(1.75,-2.75) N12(2.25,-2.75) N13(2.75,-2.75) N14(3.25,-2.75) P2(-2.75,-3.25) P3(-2.25,-3.25) P4(-1.75,-3.25) P5(-1.25,-3.25) P6(-0.75,-3.25) P7(-0.25,-3.25) P8(0.25,-3.25) P9(0.75,-3.25) P10(1.25,-3.25) P11(1.75,-3.25) P12(2.25,-3.25) P13(2.75,-3.25) P14(3.25,-3.25)
VQFN24_LM5141_160X160_1
  rect 0.61x0.254 smd: 1(-1.9,1.25) 2(-1.9,0.75) 3(-1.9,0.25) 4(-1.9,-0.25) 5(-1.9,-0.75) 6(-1.9,-1.25) 13(1.9,-1.25) 14(1.9,-0.75) 15(1.9,-0.25) 16(1.9,0.25) 17(1.9,0.75) 18(1.9,1.25)
  rect 0.254x0.61 smd: 7(-1.25,-1.9) 8(-0.75,-1.9) 9(-0.25,-1.9) 10(0.25,-1.9) 11(0.75,-1.9) 12(1.25,-1.9) 19(1.25,1.9) 20(0.75,1.9) 21(0.25,1.9) 22(-0.25,1.9) 23(-0.75,1.9) 24(-1.25,1.9)
  rect 2.794x2.794 smd: 25(0,0)
  custom 0.145x0.145 smd: A1(-1.72,1.72) A2(-1.72,-1.72) A3(1.72,-1.72) A4(1.72,1.72)
VQFN56_TPS65987D_280X280_1
  rect 0.813x0.711 smd: 1(-3.35,2.4) 3(-3.35,1.6) 11(-3.35,-1.6) 13(-3.35,-2.4)
  rect 0.711x0.203 smd: 5(-3.35,1) 6(-3.35,0.6) 7(-3.35,0.2) 8(-3.35,-0.2) 9(-3.35,-0.6) 10(-3.35,-1) 29(3.35,-2.6) 30(3.35,-2.2) 31(3.35,-1.8) 32(3.35,-1.4) 33(3.35,-1) 34(3.35,-0.6) 35(3.35,-0.2) 36(3.35,0.2) 37(3.35,0.6) 38(3.35,1) 39(3.35,1.4) 40(3.35,1.8) 41(3.35,2.2) 42(3.35,2.6)
  rect 0.203x0.711 smd: 15(-2.6,-3.35) 16(-2.2,-3.35) 17(-1.8,-3.35) 18(-1.4,-3.35) 19(-1,-3.35) 20(-0.6,-3.35) 21(-0.2,-3.35) 22(0.2,-3.35) 23(0.6,-3.35) 24(1,-3.35) 25(1.4,-3.35) 26(1.8,-3.35) 27(2.2,-3.35) 28(2.6,-3.35) 43(2.6,3.35) 44(2.2,3.35) 45(1.8,3.35) 46(1.4,3.35) 47(1,3.35) 48(0.6,3.35) 49(0.2,3.35) 50(-0.2,3.35) 51(-0.6,3.35) 52(-1,3.35) 53(-1.4,3.35) 54(-1.8,3.35) 55(-2.2,3.35) 56(-2.6,3.35)
  rect 1.753x2.591 smd: 57(-1.875,1.45)
  rect 1.753x2.54 smd: 58(-1.875,-1.475)
  rect 3.404x5.512 smd: 59(1.05,0)
VQFN-HR36-35_TPS65224_240X200_1
  custom 0.206x0.206 smd: 1(-2.5,2) 9(-2.5,-2) 19(2.5,-2) 27(2.5,2)
  rect 0.838x0.254 smd: 2(-2.775,1.5) 8(-2.775,-1.5) 20(2.775,-1.5) 26(2.775,1.5)
  rect 0.914x0.254 smd: 3(-2.738,1) 7(-2.738,-1) 21(2.738,-1) 25(2.738,1)
  rect 1.041x0.254 smd: 4(-2.675,0.5) 6(-2.675,-0.5) 22(2.675,-0.5) 24(2.675,0.5)
  custom 0.3x0.3 smd: 5(0,0)
  rect 0.254x0.838 smd: 10(-2,-2.275) 11(-1.5,-2.275) 17(1.5,-2.275) 18(2,-2.275) 28(2,2.275) 29(1.5,2.275) 35(-1.5,2.275) 36(-2,2.275)
  rect 0.254x0.914 smd: 12(-1,-2.237) 13(-0.5,-2.237) 15(0.5,-2.237) 16(1,-2.237) 30(1,2.237) 31(0.5,2.237) 33(-0.5,2.237) 34(-1,2.237)
  rect 0.254x1.702 smd: 14(0,-1.85) 32(0,1.85)
VQFNHR15_TPS630701_100X120_1
  rect 0.61x0.254 smd: 1(-1.15,0.75) 2(-1.15,0.25) 3(-1.15,-0.25) 4(-1.15,-0.75)
  rect 0.254x0.61 smd: 5(-0.725,-1.4) 6(-0.225,-1.4) 14(-0.225,1.4) 15(-0.725,1.4)
  rect 0.838x0.711 smd: 7(0.525,-1.4) 12(0.525,1.4)
  rect 1.448x0.356 smd: 9(0.775,-0.5) 11(0.775,0.5)
  rect 1.803x0.356 smd: 10(0.6,0)
VSON4_LMK6CE_80X100_SMD_1
  rect 0.889x0.66 smd: 1(-0.749,0.826) 2(-0.749,-0.826) 3(0.749,-0.826) 4(0.749,0.826)
VSON8_CSD173_130X130
  rect 0.635x0.483 smd: 1(-1.435,0.975) 2(-1.435,0.325) 3(-1.435,-0.325) 4(-1.435,-0.975)
  custom 0.577x0.577 smd: 5(0.595,0)
VSON8_CSD173_130X130_1-1
  rect 0.635x0.483 smd: 1(-1.435,0.975) 2(-1.435,0.325) 3(-1.435,-0.325) 4(-1.435,-0.975)
  custom 0.577x0.577 smd: 5(0.595,0)
VSONHR6_TPS62826_60X60_1
  rect 0.711x0.356 smd: 1(-0.65,0.5) 2(-0.65,0) 3(-0.65,-0.5)
  rect 0.991x0.203 smd: 4(0.45,-0.5) 5(0.45,0) 6(0.45,0.5)
VSSOP8_19-68_85X95
  rect 0.813x0.305 smd: 1(-1.55,0.75) 2(-1.55,0.25) 3(-1.55,-0.25) 4(-1.55,-0.75) 5(1.55,-0.75) 6(1.55,-0.25) 7(1.55,0.25) 8(1.55,0.75)
VSSOP8_19-68_85X95_0-9
  rect 0.838x0.305 smd: 1(-1.55,0.75) 2(-1.55,0.25) 3(-1.55,-0.25) 4(-1.55,-0.75) 5(1.55,-0.75) 6(1.55,-0.25) 7(1.55,0.25) 8(1.55,0.75)
WFBGA200_MT53E2G32D4DE_400X570_1-2
  round 0.33 smd: A1(-4.4,6.825) A2(-3.6,6.825) A3(-2.8,6.825) A4(-2,6.825) A5(-1.2,6.825) A8(1.2,6.825) A9(2,6.825) A10(2.8,6.825) A11(3.6,6.825) A12(4.4,6.825) AA1(-4.4,-6.175) AA2(-3.6,-6.175) AA3(-2.8,-6.175) AA4(-2,-6.175) AA5(-1.2,-6.175) AA8(1.2,-6.175) AA9(2,-6.175) AA10(2.8,-6.175) AA11(3.6,-6.175) AA12(4.4,-6.175) AB1(-4.4,-6.825) AB2(-3.6,-6.825) AB3(-2.8,-6.825) AB4(-2,-6.825) AB5(-1.2,-6.825) AB8(1.2,-6.825) AB9(2,-6.825) AB10(2.8,-6.825) AB11(3.6,-6.825) AB12(4.4,-6.825) B1(-4.4,6.175) B2(-3.6,6.175) B3(-2.8,6.175) B4(-2,6.175) B5(-1.2,6.175) B8(1.2,6.175) B9(2,6.175) B10(2.8,6.175) B11(3.6,6.175) B12(4.4,6.175) C1(-4.4,5.525) C2(-3.6,5.525) C3(-2.8,5.525) C4(-2,5.525) C5(-1.2,5.525) C8(1.2,5.525) C9(2,5.525) C10(2.8,5.525) C11(3.6,5.525) C12(4.4,5.525) D1(-4.4,4.875) D2(-3.6,4.875) D3(-2.8,4.875) D4(-2,4.875) D5(-1.2,4.875) D8(1.2,4.875) D9(2,4.875) D10(2.8,4.875) D11(3.6,4.875) D12(4.4,4.875) E1(-4.4,4.225) E2(-3.6,4.225) E3(-2.8,4.225) E4(-2,4.225) E5(-1.2,4.225) E8(1.2,4.225) E9(2,4.225) E10(2.8,4.225) E11(3.6,4.225) E12(4.4,4.225) F1(-4.4,3.575) F2(-3.6,3.575) F3(-2.8,3.575) F4(-2,3.575) F5(-1.2,3.575) F8(1.2,3.575) F9(2,3.575) F10(2.8,3.575) F11(3.6,3.575) F12(4.4,3.575) G1(-4.4,2.925) G2(-3.6,2.925) G3(-2.8,2.925) G4(-2,2.925) G5(-1.2,2.925) G8(1.2,2.925) G9(2,2.925) G10(2.8,2.925) G11(3.6,2.925) G12(4.4,2.925) H1(-4.4,2.275) H2(-3.6,2.275) H3(-2.8,2.275) H4(-2,2.275) H5(-1.2,2.275) H8(1.2,2.275) H9(2,2.275) H10(2.8,2.275) H11(3.6,2.275) H12(4.4,2.275) J1(-4.4,1.625) J2(-3.6,1.625) J3(-2.8,1.625) J4(-2,1.625) J5(-1.2,1.625) J8(1.2,1.625) J9(2,1.625) J10(2.8,1.625) J11(3.6,1.625) J12(4.4,1.625) K1(-4.4,0.975) K2(-3.6,0.975) K3(-2.8,0.975) K4(-2,0.975) K5(-1.2,0.975) K8(1.2,0.975) K9(2,0.975) K10(2.8,0.975) K11(3.6,0.975) K12(4.4,0.975) N1(-4.4,-0.975) N2(-3.6,-0.975) N3(-2.8,-0.975) N4(-2,-0.975) N5(-1.2,-0.975) N8(1.2,-0.975) N9(2,-0.975) N10(2.8,-0.975) N11(3.6,-0.975) N12(4.4,-0.975) P1(-4.4,-1.625) P2(-3.6,-1.625) P3(-2.8,-1.625) P4(-2,-1.625) P5(-1.2,-1.625) P8(1.2,-1.625) P9(2,-1.625) P10(2.8,-1.625) P11(3.6,-1.625) P12(4.4,-1.625) R1(-4.4,-2.275) R2(-3.6,-2.275) R3(-2.8,-2.275) R4(-2,-2.275) R5(-1.2,-2.275) R8(1.2,-2.275) R9(2,-2.275) R10(2.8,-2.275) R11(3.6,-2.275) R12(4.4,-2.275) T1(-4.4,-2.925) T2(-3.6,-2.925) T3(-2.8,-2.925) T4(-2,-2.925) T5(-1.2,-2.925) T8(1.2,-2.925) T9(2,-2.925) T10(2.8,-2.925) T11(3.6,-2.925) T12(4.4,-2.925) U1(-4.4,-3.575) U2(-3.6,-3.575) U3(-2.8,-3.575) U4(-2,-3.575) U5(-1.2,-3.575) U8(1.2,-3.575) U9(2,-3.575) U10(2.8,-3.575) U11(3.6,-3.575) U12(4.4,-3.575) V1(-4.4,-4.225) V2(-3.6,-4.225) V3(-2.8,-4.225) V4(-2,-4.225) V5(-1.2,-4.225) V8(1.2,-4.225) V9(2,-4.225) V10(2.8,-4.225) V11(3.6,-4.225) V12(4.4,-4.225) W1(-4.4,-4.875) W2(-3.6,-4.875) W3(-2.8,-4.875) W4(-2,-4.875) W5(-1.2,-4.875) W8(1.2,-4.875) W9(2,-4.875) W10(2.8,-4.875) W11(3.6,-4.875) W12(4.4,-4.875) Y1(-4.4,-5.525) Y2(-3.6,-5.525) Y3(-2.8,-5.525) Y4(-2,-5.525) Y5(-1.2,-5.525) Y8(1.2,-5.525) Y9(2,-5.525) Y10(2.8,-5.525) Y11(3.6,-5.525) Y12(4.4,-5.525)
WFQFN24_CDCE6214-Q1_160X160_0-9
  rect 0.61x0.254 smd: 1(-1.9,1.25) 2(-1.9,0.75) 3(-1.9,0.25) 4(-1.9,-0.25) 5(-1.9,-0.75) 6(-1.9,-1.25) 13(1.9,-1.25) 14(1.9,-0.75) 15(1.9,-0.25) 16(1.9,0.25) 17(1.9,0.75) 18(1.9,1.25)
  rect 0.254x0.61 smd: 7(-1.25,-1.9) 8(-0.75,-1.9) 9(-0.25,-1.9) 10(0.25,-1.9) 11(0.75,-1.9) 12(1.25,-1.9) 19(1.25,1.9) 20(0.75,1.9) 21(0.25,1.9) 22(-0.25,1.9) 23(-0.75,1.9) 24(-1.25,1.9)
  rect 2.794x2.794 smd: 25(0,0)
  rect 0.254x0.254 smd: A1(-1.75,1.75) A2(-1.75,-1.75) A3(1.75,-1.75) A4(1.75,1.75)
WQFN24_19-68_160X160
  rect 0.813x0.305 smd: 1(-2,1.25) 2(-2,0.75) 3(-2,0.25) 4(-2,-0.25) 5(-2,-0.75) 6(-2,-1.25) 13(2,-1.25) 14(2,-0.75) 15(2,-0.25) 16(2,0.25) 17(2,0.75) 18(2,1.25)
  rect 0.305x0.813 smd: 7(-1.25,-2) 8(-0.75,-2) 9(-0.25,-2) 10(0.25,-2) 11(0.75,-2) 12(1.25,-2) 19(1.25,2) 20(0.75,2) 21(0.25,2) 22(-0.25,2) 23(-0.75,2) 24(-1.25,2)
  rect 2.692x2.692 smd: 25(0,0)
WSON6_CSD13202Q2_80X80_0-8
  rect 0.457x0.305 smd: 1(-0.975,0.65) 2(-0.975,0) 3(-0.975,-0.65) 4(0.975,-0.65) 5(0.975,0) 6(0.975,0.65)
  rect 0.762x0.305 smd: 7(0.095,-0.65)
  rect 0.991x0.94 smd: 8(0,0.325)
WSON6_TPS717_60X60_0-8
  rect 0.838x0.279 smd: 1(-0.525,0.5)
  rect 0.762x0.279 smd: 2(-0.575,0) 3(-0.575,-0.5) 4(0.575,-0.5) 5(0.575,0) 6(0.575,0.5)
WSON8_19-68_80X80_0-8
  rect 0.711x0.305 smd: 1(-1.05,0.75) 2(-1.05,0.25) 3(-1.05,-0.25) 4(-1.05,-0.75) 5(1.05,-0.75) 6(1.05,-0.25) 7(1.05,0.25) 8(1.05,0.75)
  rect 0.965x1.702 smd: 9(0,0)
X2SON3_ESD122DMX_30X40_0-4
  rect 0.203x0.203 smd: 1(-0.15,0) 2(0.15,-0.34) 3(0.15,0.34)
X2SON5_TLV7021_30X30_0-4
  custom 0.08x0.08 smd: 1(-0.39,0.24) 2(-0.39,-0.24) 4(0.39,-0.24) 5(0.39,0.24)
  rect 0.356x0.356 smd rot 45: 3(0,0)
X2SON8_15-74_70X50
  rect 0.838x0.203 smd: 1(-0.55,0.6) 2(-0.55,0.2) 3(-0.55,-0.2) 4(-0.55,-0.6) 5(0.55,-0.6) 6(0.55,-0.2) 7(0.55,0.2) 8(0.55,0.6)
X2SON8_TXS0102_40X60_0-4
  rect 0.61x0.178 smd: 1(-0.4,0.525)
  rect 0.508x0.178 smd: 2(-0.45,0.175) 3(-0.45,-0.175) 4(-0.45,-0.525) 5(0.45,-0.525) 6(0.45,-0.175) 7(0.45,0.175) 8(0.45,0.525)
XTAL4_ABM8_130X110_0-8_SMD
  rect 1.321x1.092 smd: 1(-1.15,-0.875) 2(1.15,-0.875) 3(1.15,0.875) 4(-1.15,0.875)
XTAL4_ABMM_280X200_SMD_1-3
  rect 2.21x1.397 smd: 1(-3.15,-1.27) 2(-3.15,1.27) 3(3.15,1.27)
  rect 2.388x1.397 smd: 4(3.05,-1.27)
XTAL4_XRCGB-FM_80X60_SMD_0-7
  rect 0.762x0.711 smd: 1(-0.675,-0.5) 2(0.675,-0.5) 3(0.675,0.5) 4(-0.675,0.5)
XTAL_ABM3_205X130_SMD_1-4
  rect 1.803x2.413 smd: 1(-1.9,0) 2(1.9,0)
XTAL_ECS-32_130X60_SMD_0-9
  rect 1.118x1.905 smd: 1(-1.25,0) 2(1.25,0)

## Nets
AVDD_3V3_DAC: C29.1 C30.1 C31.1 C32.1 C349.1 C350.1 C351.1 C352.1 FL1.2 U5.23(AVDD) U6.23(AVDD) U76.23(AVDD) U77.23(AVDD)
DGND: C1.2 C2.2 C3.2 C4.2 C6.2 C7.2 C9.2 C10.2 C11.1 C13.1 C15.1 C17.1 C19.2 C20.1 C21.1 C22.1 C23.1 C28.2 C29.2 C30.2 C31.2 C32.2 C33.1 C34.2 C35.2 C36.2 C37.2 C38.2 C39.2 C40.2 C41.2 C42.2 C43.2 C44.2 C45.2 C46.2 C47.2 C48.2 C49.2 C50.2 C51.2 C52.2 C53.1 C54.2 C55.2 C56.2 C57.2 C58.2 C59.2 C60.1 C61.2 C62.2 C63.2 C64.2 C65.2 C66.2 C67.2 C68.2 C69.2 C70.2 C71.2 C72.2 C73.2 C74.2 C75.2 C76.2 C77.2 C78.2 C79.2 C80.2 C81.2 C82.2 C83.2 C84.2 C85.2 C86.2 C87.2 C88.1 C89.2 C90.2 C91.2 C92.1 C93.1 C94.2 C95.2 C96.2 C97.1 C98.2 C99.2 C100.2 C101.2 C102.1 C103.1 C104.1 C105.2 C106.1 C107.2 C108.2 C109.2 C110.2 C111.2 C112.2 C113.2 C114.2 C115.2 C116.2 C117.2 C118.2 C119.2 C120.2 C121.2 C122.1 C123.2 C124.2 C125.1 C126.1 C127.2 C128.2 C129.2 C130.2 C131.2 C132.2 C133.2 C134.2 C135.2 C136.2 C137.2 C138.2 C139.2 C140.2 C141.2 C142.2 C143.2 C144.2 C145.2 C146.2 C147.2 C148.2 C149.1 C150.1 C151.1 C152.2 C153.2 C154.2 C155.2 C156.2 C157.2 C158.2 C159.2 C160.2 C161.2 C162.2 C163.2 C164.2 C165.1 C166.2 C167.2 C168.2 C169.2 C170.2 C171.2 C172.2 C173.2 C174.2 C175.2 C176.2 C177.2 C178.2 C179.2 C180.2 C181.1 C182.2 C183.2 C184.1 C185.1 C186.1 C187.1 C188.2 C189.1 C190.2 C191.1 C192.2 C193.2 C194.2 C195.2 C196.2(GND) C197.2 C198.2(GND) C199.1 C200.2 C201.2 C202.2 C203.1 C204.2 C205.1 C206.2 C207.2 C208.2 C209.1 C210.2(GND) C211.2 C212.2 C213.1 C214.2(GND) C215.1 C216.1 C217.1 C218.2 C219.2 C220.1 C221.2 C222.2 C223.1 C224.2 C225.1 C226.2 C227.2 C228.2 C229.2 C230.1 C231.1 C232.2 C233.2 C234.2 C235.1 C236.1 C237.2 C238.2 C239.2 C240.2 C241.2 C242.2 C244.2 C245.2 C246.2 C247.1 C248.2 C249.2 C250.2 C251.1 C252.2 C253.2 C254.2 C255.2 C256.2 C257.2 C258.2 C259.2 C260.2 C261.2 C262.1 C263.2 C264.1 C265.2 C266.1 C267.2 C268.1 C269.2 C270.2 C271.2 C272.2 C273.2 C274.2 C275.1 C276.2 C277.2 C278.2 C279.2 C280.1 C281.1 C282.1 C283.1 C284.1 C285.2 C286.1 C287.1 C288.1 C289.1 C290.2 C291.1 C292.2 C293.2 C294.2 C295.2 C296.2 C297.2 C298.2 C299.2 C300.1 C301.2 C302.2 C303.2 C304.2 C305.2 C306.2 C307.2 C308.2 C309.2 C310.2 C311.2 C312.2 C314.2 C315.2 C316.2 C319.1 C320.1 C321.2 C322.2 C323.2 C324.2 C325.2 C326.2 C327.2 C328.2 C329.2 C330.2 C332.1 C334.1 C336.1 C338.1 C339.2 C340.2 C341.1 C342.1 C343.1 C344.1 C349.2 C350.2 C351.2 C352.2 C353.2 C354.2 C355.2 C356.2 C357.2 C358.2 C359.2 C360.2 C361.2 C362.2 C363.2 C364.2 C365.2 C366.2 C367.2 C368.2 C369.2 C370.2 C371.2 C372.2 C373.2 C374.2 C375.2 C376.2 C377.2 C378.2 C379.2 C380.2 C381.2 C382.2 C383.2 C384.2 C385.2 C386.2 C387.2 C388.2 C389.2 C390.2 C391.1 C392.1 C393.1 C394.1 C395.2 C396.1 C397.2 C398.2 C399.2 C400.2 C401.2 C402.2 C403.2 C404.2 C405.2 C406.2 C407.2 C408.2 C409.1 C410.2 C411.2 C412.2 C413.2 C414.1 C415.1 C416.1 C417.2 C418.2 C419.1 C420.1 C421.1 C422.2(GND) C423.2 C424.2 C425.1 C426.2 C427.2 C429.2 C430.1 C431.2 C432.2 C433.2 C434.2 C435.2 C436.2 C437.2 C438.2 C439.2 C440.2 C441.2 C442.2(GND) C443.2 C444.2 C445.2 C446.2 C447.2 C448.2 C449.1 C450.2 C451.2 C452.2 C453.2 C454.2 C455.1 C456.2 C457.2 C458.2 C459.2 C460.2 C461.2 C462.2 C463.2 C464.2 C465.2 C466.2 C467.2 C468.2 C469.1 C470.1 C471.2 C472.2 C473.1 C474.2 C475.2 C476.2 C477.2 C478.1 C479.2 C480.2 C481.2(GND) C482.2(GND) C483.2 C484.2 C485.2 C486.2 C487.2 C488.2 C489.1 C490.2 C491.2 C492.2 C493.2 C494.2 C495.2 C496.2 C497.2 C498.2 C499.2 C500.1 C501.2 C502.2 C503.2 C504.2 C505.2 C506.2 C507.2 C508.2 C509.2 C510.2 C511.1 C512.2 C513.2 C514.2 C515.1 C516.1 C517.2 C518.2 C519.1 C520.2 C521.2 C522.2 C523.1 C525.2 C526.2 C527.2 C528.1 C529.1 C530.2 C531.2 C532.2 C533.2 C534.2 C535.2 C536.2 C537.2 C538.2 C539.2 C540.2 C541.1 C542.2 C543.1 C544.2 C545.1 C546.2 C547.2 C548.2 C549.2 C550.2 C551.2 C552.2 C553.2 C554.2 C555.2 C556.2 C557.2 C558.2 C560.2 C561.2 C562.2 C563.2 C564.2 C565.2 C566.2 C567.2 C568.2 C569.2 C570.2 C571.2 C572.2 C573.2 C574.1 C575.1 C576.2 C577.2 C578.2 C579.2 C580.2 C581.2 C582.2 C583.2 C584.1 C585.2 C586.2 C587.1 C588.2 C589.2 C590.2 C591.2 C592.2 C593.2 C594.1 C595.2 C596.2 C598.2 C599.1 C601.2 C602.2 C604.2 C605.1 C606.1 C607.1 C608.1 C609.1 C610.2 C611.2 C612.1 C613.1 C614.2 C616.2 C617.1 C618.1 C619.1 C620.2 C621.1 C622.1 C623.2 C624.2 C625.1 C626.2 C627.2 C628.2 C630.2 C631.2 C632.2 C633.2 C635.2 C636.2 C637.2 C641.2 C642.2 C643.2 C644.2 C645.2 C646.2 C647.2 C648.2 C649.2 C650.2 C651.2 C652.2 C653.2 C654.2 C655.2 C656.2 C657.2(GND) C658.2(GND) C659.2(GND) C660.2(GND) C661.2(GND) C662.2(GND) C663.2(GND) C664.2(GND) C665.2(GND) C666.2(GND) C667.2(GND) C668.2(GND) C669.2(GND) C670.2(GND) D1.1 D2.1(A) D3.1 D4.1(A) D6.1(A) D7.2(ANODE) D8.2(ANODE) D9.1(GND) D10.1 D11.1 D12.1 D13.1 D14.1 D16.2(ANODE) D17.2(ANODE) J1.1A J1.1B J2.1A J2.1B J3.1A J3.1B J4.1A J4.1B J5.1 J5.3 J6.1 J6.3 J7.2 J8.6 J9.2 J11.6 J12.7 J12.8 J12.15 J12.16 J12.22 J12.25 J12.26 J12.31 J12.35 J12.36 J12.45 J12.46 J12.49 J12.50 J12.57 J12.58 J12.65 J12.66 J12.75 J12.76 J12.81(GND1) J12.82(GND2) J12.83(GND3) J12.84(GND4) J12.85(GND5) J12.86(GND6) J12.87(GND7) J12.88(GND8) J13.7 J13.8 J13.15 J13.16 J13.22 J13.25 J13.26 J13.31 J13.35 J13.36 J13.45 J13.46 J13.49 J13.50 J13.57 J13.58 J13.65 J13.66 J13.75 J13.76 J13.81(GND1) J13.82(GND2) J13.83(GND3) J13.84(GND4) J13.85(GND5) J13.86(GND6) J13.87(GND7) J13.88(GND8) J14.10 J14.12 J14.16 J14.20 J15.2 J16.2 J17.5(GND) J18.1 J18.5 J18.8 J18.15 J18.16 J18.17 J18.18 J18.21 J18.24 J18.31 J18.32 J18.33 J18.34 J18.41 J19.1 J19.5 J19.8 J19.15 J19.16 J19.17 J19.18 J19.21 J19.24 J19.31 J19.32 J19.33 J19.34 J19.41 J20.2 J21.2 J21.10 J22.5(GND) J23.4(GND) J24.A1(GND#A1) J24.A12(GND#A12) J24.B1(GND#B1) J24.B12(GND#B12) J25.A1(GND#A1) J25.A12(GND#A12) J25.B1(GND#B1) J25.B12(GND#B12) J26.6(VSS) J26.SH1 J26.SH2 J26.SH3 J26.SH4 LD3.1(CATHODE) LD5.1(CATHODE) LD6.1(CATHODE) LD8.1(CATHODE) LD9.1(CATHODE) MOD1.2(GND) Q1.4(S1) Q1.7(S2) Q2.2(EMITTER) Q3.2(S) Q5.4(S1) Q5.7(S2) Q6.3(D) Q7.3(D) Q10.4(S1) Q10.7(S2) Q11.1(1S) Q11.2(2S) Q11.3(3S) R1.2 R2.2 R22.2 R26.2 R27.2 R30.2 R31.2 R32.2 R36.1 R37.1 R48.2 R49.2 R61.2 R63.2 R68.1 R71.2 R76.2 R85.2 R94.2 R100.2 R103.1 R107.2 R109.2 R112.1 R143.2 R145.2 R146.2 R147.2 R148.2 R149.2 R150.2 R151.2 R152.2 R153.2 R154.2 R155.2 R156.2 R157.2 R158.2 R159.2 R160.2 R181.1 R194.2 R202.2 R203.1 R214.1 R217.1 R218.2 R226.2 R229.1 R230.1 R231.1 R232.1 R238.2 R245.1 R247.2 R250.1 R254.1 R258.2 R274.1 R278.1 R289.2 R303.2 R313.2 R320.2 R325.2 R341.1 R355.1 R365.2 R367.2 R369.2 R370.2 R372.2 R373.2 R381.2 R383.2 R385.1 R391.2 R403.2 R404.2 R415.1 R417.1 R418.1 R422.1 R426.2 R427.1 R428.2 R429.2 R430.2 R438.1 R442.1 R451.2 R456.2 R458.2 R462.1 R467.2 R488.2 R489.1 R490.1 R504.2 R531.1 R545.2 R553.2 R555.1 R556.2 R557.2 R560.2 R561.2 R562.2 R564.2 R567.2 R569.1 R573.2 R588.1 R591.1 R606.2 R607.2 R609.1 R610.1 R613.1 R618.1 R622.1 R623.1 R624.1 R626.1 R628.1 R632.2 R635.1 R639.1 R642.1 R648.2 R662.2 R666.2 R672.2 R681.2 R682.2 R683.2 SW4.1 SW4.4 SW5.1 SW5.4 SW6.1 SW6.4 SW7.1 SW7.4 SW8.1 SW8.4 TP1.1(TP) TP2.1(TP) TP40.1(TP) TP41.1(TP) TP42.1(TP) TP44.1(TP) TP77.1(TP) TP85.1(TP) TP106.1(TP) U1.3(GND) U2.2(GND) U3.10(AGND) U3.16(DGND1) U3.30(DGND2) U3.43(DGND3) U3.44(BGND) U4.2(GND) U5.25(EP_PAD) U5.A1(VSS#A1) U5.A2(VSS#A2) U5.A3(VSS#A3) U5.A4(VSS#A4) U6.25(EP_PAD) U6.A1(VSS#A1) U6.A2(VSS#A2) U6.A3(VSS#A3) U6.A4(VSS#A4) U7.8(AVSS) U7.33(VSS) U8.8(AVSS) U8.33(VSS) U9.2(GND) U10.5(GND) U11.2(GND) U12.4(GND) U13.3(GND) U14.3(GND) U15.25(EP) U15.A1(GND#A1) U15.A2(GND#A2) U15.A3(GND#A3) U15.A4(GND#A4) U16.4(GND) U17.2(GND) U18.9(GND) U18.25(PAD) U19.3(GND) U20.6(SSEN) U20.7(OEB) U20.21(EP_GND) U21.25(GND) U21.33(EP) U22.7(VSS) U22.11(EP) U23.3(GND) U24.2(GND) U25.4(GND) U26.3(GND) U27.3(GND) U28.B3(VSS) U28.C1(VSSQ#C1) U28.E5(VSSQ#E5) U29.5(GND) U30.3(GND) U31.3(GND) U32.7(GND) U33.3(GND) U34.7(GND) U35.3(GND) U36.3(GND) U37.6(GND) U38.2(GND) U39.4(GND) U40.7(GND) U41.1(ANODE) U42.5(GND) U42.9(EP) U43.2(GND) U44.2(GND) U45.7(GND) U46.2(GND) U47.A1(VSS#A1) U47.A4(VSS#A4) U47.A6(VSS#A6) U47.A10(VSS#A10) U47.A13(VSS#A13) U47.A18(VSS#A18) U47.A22(VSS#A22) U47.AA2(VSS#AA2) U47.AA4(VSS#AA4) U47.AA8(VSS#AA8) U47.AA11(VSS#AA11) U47.AA14(VSS#AA14) U47.AB1(VSS#AB1) U47.AB3(VSS#AB3) U47.AB5(VSS#AB5) U47.AB9(VSS#AB9) U47.AB12(VSS#AB12) U47.AB15(VSS#AB15) U47.AB18(VSS#AB18) U47.AB22(VSS#AB22) U47.B3(VSS#B3) U47.B5(VSS#B5) U47.B7(VSS#B7) U47.C4(VSS#C4) U47.D2(VSS#D2) U47.D4(VSS#D4) U47.D11(VSS#D11) U47.D20(VSS#D20) U47.E1(VSS#E1) U47.E3(VSS#E3) U47.E5(VSS#E5) U47.F2(VSS#F2) U47.F4(VSS#F4) U47.F11(VSS#F11) U47.F13(VSS#F13) U47.F16(VSS#F16) U47.G3(VSS#G3) U47.G5(VSS#G5) U47.G9(VSS#G9) U47.G12(VSS#G12) U47.G17(VSS#G17) U47.H1(VSS#H1) U47.H4(VSS#H4) U47.H11(VSS#H11) U47.H14(VSS#H14) U47.H20(VSS#H20) U47.J3(VSS#J3) U47.J12(VSS#J12) U47.J17(VSS#J17) U47.K1(VSS#K1) U47.K4(VSS#K4) U47.K7(VSS#K7) U47.K9(VSS#K9) U47.K11(VSS#K11) U47.L3(VSS#L3) U47.L12(VSS#L12) U47.L14(VSS#L14) U47.L20(VSS#L20) U47.M4(VSS#M4) U47.M7(VSS#M7) U47.M11(VSS#M11) U47.M17(VSS#M17) U47.N1(VSS#N1) U47.N8(VSS#N8) U47.N10(VSS#N10) U47.N12(VSS#N12) U47.N14(VSS#N14) U47.N16(VSS#N16) U47.P7(VSS#P7) U47.P11(VSS#P11) U47.P13(VSS#P13) U47.P15(VSS#P15) U47.P17(VSS#P17) U47.P20(VSS#P20) U47.R2(VSS#R2) U47.R4(VSS#R4) U47.R6(VSS#R6) U47.R10(VSS#R10) U47.R12(VSS#R12) U47.R14(VSS#R14) U47.R16(VSS#R16) U47.T1(VSS#T1) U47.T3(VSS#T3) U47.T5(VSS#T5) U47.T7(VSS#T7) U47.T15(VSS#T15) U47.T17(VSS#T17) U47.U2(VSS#U2) U47.U4(VSS#U4) U47.U6(VSS#U6) U47.U9(VSS#U9) U47.U12(VSS#U12) U47.U14(VSS#U14) U47.U16(VSS#U16) U47.V1(VSS#V1) U47.V3(VSS#V3) U47.V5(VSS#V5) U47.V7(VSS#V7) U47.V9(VSS#V9) U47.V20(VSS#V20) U47.W2(VSS#W2) U47.W4(VSS#W4) U47.W6(VSS#W6) U47.W8(VSS#W8) U47.W11(VSS#W11) U47.W14(VSS#W14) U47.Y3(VSS#Y3) U47.Y5(VSS#Y5) U47.Y9(VSS#Y9) U47.Y12(VSS#Y12) U47.Y15(VSS#Y15) U48.10(GNDA) U48.17(GND#17) U48.48(GND#48) U48.55(GND#55) U48.58(GND#58) U48.64(W\A\K\E\) U48.66(XOSC0) U48.80(GND#80) U48.114(GND#114) U49.A6(VSS#A6) U49.C4(VSSQ#C4) U49.E7(VSS#E7) U49.G5(VSS#G5) U49.H10(VSS#H10) U49.J5(VSS#J5) U49.K8(VSS#K8) U49.N2(VSSQ#N2) U49.N5(VSSQ#N5) U49.P4(VSSQ#P4) U49.P6(VSSQ#P6) U50.4(GND) U51.4(GND) U52.2(GND) U54.2(GND) U55.6(GND) U55.9(PAD) U56.5(AGND) U56.6(FB_B2) U56.14(PGND_B34) U56.32(PGND_B12) U57.5(GND) U57.9(E\N\) U58.A3(VSS#A3) U58.A10(VSS#A10) U58.AB3(VSS#AB3) U58.AB5(VSS#AB5) U58.AB8(VSS#AB8) U58.AB10(VSS#AB10) U58.C1(VSS#C1) U58.C5(VSS#C5) U58.C8(VSS#C8) U58.C12(VSS#C12) U58.D2(VSS#D2) U58.D4(VSS#D4) U58.D9(VSS#D9) U58.D11(VSS#D11) U58.E1(VSS#E1) U58.E5(VSS#E5) U58.E8(VSS#E8) U58.E12(VSS#E12) U58.G1(VSS#G1) U58.G3(VSS#G3) U58.G5(VSS#G5) U58.G8(VSS#G8) U58.G10(VSS#G10) U58.G12(VSS#G12) U58.J1(VSS#J1) U58.J3(VSS#J3) U58.J10(VSS#J10) U58.J12(VSS#J12) U58.K2(VSS#K2) U58.K4(VSS#K4) U58.K9(VSS#K9) U58.K11(VSS#K11) U58.N2(VSS#N2) U58.N4(VSS#N4) U58.N9(VSS#N9) U58.N11(VSS#N11) U58.P1(VSS#P1) U58.P3(VSS#P3) U58.P10(VSS#P10) U58.P12(VSS#P12) U58.T1(VSS#T1) U58.T3(VSS#T3) U58.T5(VSS#T5) U58.T8(VSS#T8) U58.T10(VSS#T10) U58.T12(VSS#T12) U58.V1(VSS#V1) U58.V5(VSS#V5) U58.V8(VSS#V8) U58.V12(VSS#V12) U58.W2(VSS#W2) U58.W4(VSS#W4) U58.W9(VSS#W9) U58.W11(VSS#W11) U58.Y1(VSS#Y1) U58.Y5(VSS#Y5) U58.Y8(VSS#Y8) U58.Y12(VSS#Y12) U59.4(GND) U59.9(EP) U60.3(GND) U61.5(VSS) U62.2(GND) U63.2(GND) U64.1(GND1) U64.5(GND2) U64.10(AGND) U64.11(GND3) U64.13(TEST) U64.15(GND4) U64.25(GND5) U64.35(GND6) U64.47(GND7) U64.51(GND8) U65.4(GND) U66.3(GND) U66.7(EP) U67.4(GND) U68.2(GND) U69.4(GND) U70.4(GND) U70.9(EPAD) U71.3(GND) U72.4(GND) U72.10(PGND) U72.15(VSEL) U73.4(GND) U73.7(EP) U74.1(GND) U75.3(GND) U76.25(EP_PAD) U76.A1(VSS#A1) U76.A2(VSS#A2) U76.A3(VSS#A3) U76.A4(VSS#A4) U77.25(EP_PAD) U77.A1(VSS#A1) U77.A2(VSS#A2) U77.A3(VSS#A3) U77.A4(VSS#A4) U78.6(GND) U79.2(GND) U80.10(GND1) U80.11(GND2) U81.11(GND1) U81.12(GND2) U81.13(GND3) U81.25(EP) U82.25(GND) U82.33(EP) U83.11(GND1) U83.12(GND2) U83.13(GND3) U83.25(EP) U84.49(EP) U85.49(EP) U86.2(GND) U87.3(GND) U88.3(GND) U89.3(GND) U90.3(A2) U90.5(GND) U90.6(B2) U91.2(A0) U91.7(GND) U92.B3(A0) U92.C1(GND) U93.3(GND) U97.10(GND1) U97.11(GND2) U98.4(GND) U102.4(GND) U107.4(GND) U109.3(A2) U109.5(GND) U109.6(B2) U110.10(GND1) U110.11(GND2) U113.B3(A0) U113.C1(GND) U113.C3(A1) U114.1(A1) U114.2(A0) U114.7(GND) U115.C1(GND) U115.C3(A1) U116.1(A1) U116.7(GND) U117.1(1\O\E\) U117.10(GND1) U117.11(GND2) U117.16(2\O\E\) U118.7(GND) U119.C1(GND) U120.2(GND) U121.C1(GND) U122.7(GND) U123.C1(GND) U124.7(GND) U125.1(1\O\E\) U125.7(1A2) U125.9(2A2) U125.10(GND1) U125.11(GND2) U125.12(2B2) U125.14(1B2) U125.16(2\O\E\) U126.1(1\O\E\) U126.7(1A2) U126.9(2A2) U126.10(GND1) U126.11(GND2) U126.12(2B2) U126.14(1B2) U126.16(2\O\E\) U127.4(GND) U128.3(AGND) U128.6(OSC) U128.9(PGND) U128.16(VCCX) U128.25(EP) U128.A1 U128.A2 U128.A3 U128.A4 U129.20(GND#20) U129.51(GND#51) U129.59(GND#59) U130.4(GND) U132.1(GND#1) U132.2(GND#2) U132.3(GND#3) U132.7(GND#7) U133.1(GND#1) U133.2(GND#2) U133.3(GND#3) U133.7(GND#7) Y1.2 Y1.4 Y2.2(GND1) Y2.4(GND2) Y3.2 Y3.4 Y5.2 Y5.4
DVDD1V8_ALERT: R305.1 U123.A3(ALERT) U124.3(ALERT)
DVDD3V3: C252.1 R244.1 U56.21(VOUT_LDO2)
DVDD3V3_ALERT: R505.1 U91.3(ALERT) U92.A3(ALERT)
V3V3_OPTICAL: C1.1 L1.2 MOD1.1(VCC)
VBAT_IN: C49.1 C55.1 C95.1 C100.1 J7.1 U7.21(VBAT_IN) U8.21(VBAT_IN)
VBUS_5V0_TYPEA: C316.1 C637.1 C645.1 J23.1(VCC) R389.2 TP105.1(TP) U74.6(OUT1) U74.7(OUT2) U74.8(OUT3) U130.6(VBUS)
VBUS_TYPEC1: C321.1 C326.1 C327.1 C641.1 C643.1 C654.1 C655.1 D5.1(A1) J24.A4(VBUS1) J24.A9(VBUS2) J24.B4(VBUS3) J24.B9(VBUS4) R397.1 TP107.1(TP) U129.13(VBUS1) U133.4(IN1) U133.5(IN2) U133.6(IN3)
VBUS_TYPEC2: C325.1 C638.1 C642.1 C644.1 C646.1 C647.1 C649.1 C650.1 C652.1 C653.1 D5.2(A2) J25.A4(VBUS1) J25.A9(VBUS2) J25.B4(VBUS3) J25.B9(VBUS4) Q8.4(D1) Q8.7(D2) R401.2 R402.1 R675.1 TP108.1(TP) U129.3(VBUS2) U132.4(IN1) U132.5(IN2) U132.6(IN3)
VCC1V1: C258.1 C259.1 C260.1 C592.1 L7.2 R327.1
VCC1V1_N: R327.3 R599.2
VCC1V1_P: R327.2 R600.2
VCC1V1_SW: L7.1 U56.15(SW_B4)
VCC1V8_CLKBUF: C265.1 C266.2 C284.2 C286.2 FL10.1 R329.2 R348.2 U62.4(VDD) U65.6(VDD)
VCC1V8_SYS: C72.1 C73.1 C75.1 C76.1 C101.1 C102.2 C106.2 C137.1 C138.1 C141.1 C142.1 C144.1 C146.1 C148.1 C149.2 C151.2 C160.1 C161.1 C164.1 C167.1 C168.1 C177.1 C179.1 C195.1 C220.2 C242.1 C256.1 C257.1 C261.1 C371.1 C372.1 C373.1 C374.1 C376.1 C381.1 C388.1 C389.1 C390.1 C395.1 C396.2 C408.1 C421.2 C503.1 C514.1 C518.1 C593.1 C608.2 C617.2 FL5.1 FL11.1 FL12.1 J12.10 J12.12 J13.10 J13.12 L6.2 R28.2 R29.1 R33.1 R35.2 R67.2 R69.1 R70.2 R75.1 R80.2 R83.1 R96.1 R97.2 R114.1 R117.1 R122.2 R123.2 R124.2 R161.2 R164.2 R166.1 R196.2 R198.1 R200.1 R242.1 R248.2 R262.1 R263.1 R264.1 R266.1 R267.1 R268.1 R269.1 R270.1 R275.1 R279.2 R334.2 R361.1 R375.1 R419.2 R423.2 R434.2 R436.1 R443.2 R444.2 R445.2 R446.2 R447.2 R448.2 R449.2 R450.2 R452.2 R454.2 R464.1 R465.1 R503.1 R508.1 R532.1 R565.1 R575.1 R611.1 R612.1 R614.2 R631.1 R636.2 U5.6(IOVDD) U6.6(IOVDD) U11.3(VCCA) U12.1(VCC) U17.5(SHDN/VIO) U24.3(VCCA) U26.5(VCC) U27.5(VCC) U28.B4(VCC) U28.D1(VCCQ#D1) U28.E4(VCCQ#E4) U29.8(VCCB) U32.1(VCCA) U34.1(VCCA) U37.1(VCCA) U43.5(VCC) U45.1(VCCA) U49.C6(VCCQ#C6) U49.M4(VCCQ#M4) U49.N4(VCCQ#N4) U49.P3(VCCQ#P3) U49.P5(VCCQ#P5) U50.8(VCC) U56.26(PVIN_LDO3) U76.6(IOVDD) U77.6(IOVDD) U78.1(VCCA) U79.3(VCCA) U80.2(VCCB) U81.23(VCCB1) U81.24(VCCB2) U83.23(VCCB1) U83.24(VCCB2) U125.3(VCCA) U126.3(VCCA)
VCC1V8_SYS_N: R334.4 R335.2
VCC1V8_SYS_P: R331.2 R334.1
VCC1V8_SYS_SW: L6.1 U56.13(SW_B3)
VCC1V8_VDD18: C10.1 C19.1 C79.1 C80.1 C83.1 C91.1 C94.1 C157.1 C162.1 FL5.2 R47.1 R50.1 R53.2 R59.2 R72.2 R144.1 R424.2 R425.2 U3.17(VDD18) U3.42(VIO) U9.4(VDD) U13.5(VCC) U30.5(VCC) U31.5(VCC)
VCC2V5_PG: R637.1 U127.2(PG)
